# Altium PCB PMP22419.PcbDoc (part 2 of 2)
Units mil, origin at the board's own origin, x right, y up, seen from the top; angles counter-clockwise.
Board outline 4300 x 2100 mil, 4 copper layers (Top Layer, Signal Layer 1, Signal Layer 2, Bottom Layer), stack 66.4 mil thick; 128 components, 54 nets, 301 pads, 317 vias.
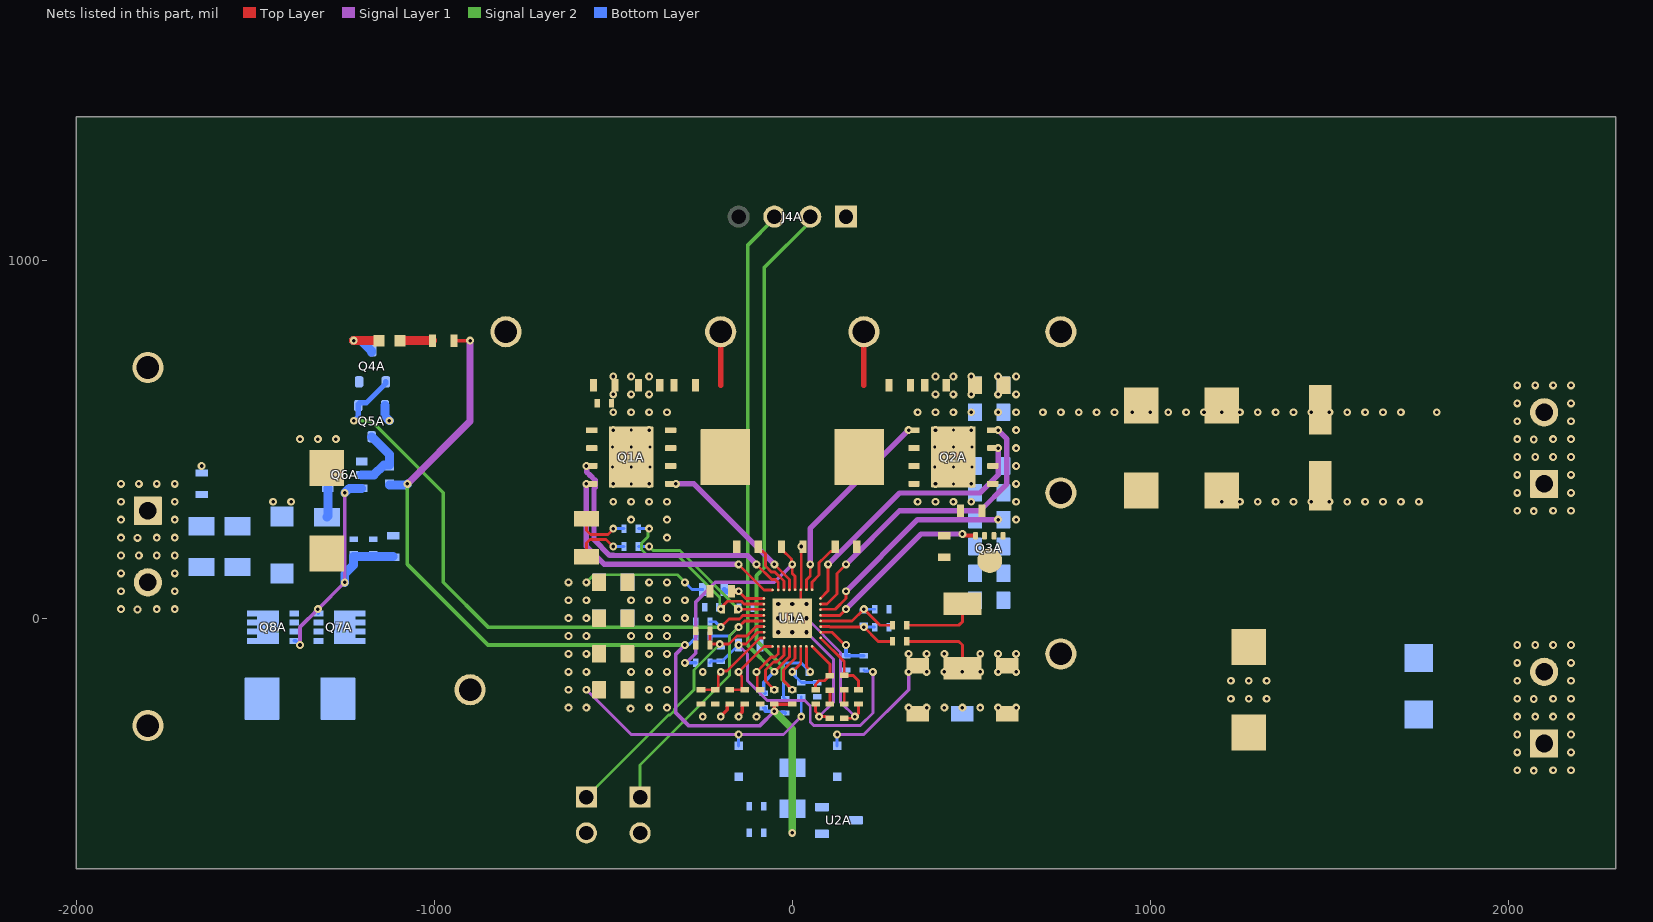
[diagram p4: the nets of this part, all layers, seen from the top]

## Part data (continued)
R31A: library part CMP-0026893-2, "RES, 2.0 M, 5%, 0.063 W, AEC-Q200 Grade 0, 0402", Manufacturer=Vishay-Dale, Power_W=63mW, Supplier Part Number 1=541-2.0MJCT-ND, TempCo="200 ppm/C", Tolerance_%=5%, Value2=0.063W, Value_Code=2M00, ValueDisplayed=2.0M
SH-JP1A: library part CMP-0003623-3, "Shunt, 100mil, Gold plated, Black", Alternate Manufacturer=3M, Alternate PartNumber=969102-0000-DA, Manufacturer=Samtec, Supplier Part Number 1=SAM8858-ND
TP1A TP2A: library part CMP-0055149-1, "Test Point, Multipurpose, White, TH", Color=White, Manufacturer=Keystone, Supplier Part Number 1=36-5012-ND
TP3A TP4A TP8A: library part CMP-0055148-1, "Test Point, Multipurpose, Black, TH", Color=Black, Manufacturer=Keystone, Supplier Part Number 1=36-5011-ND
TP5A TP6A TP7A TP9A: library part CMP-0055147-1, "Test Point, Multipurpose, Red, TH", Color=Red, Manufacturer=Keystone, Supplier Part Number 1=36-5010-ND
U1A: library part CMP-0089011-2, "No description", Manufacturer="Texas Instruments", Operating Temperature Range=to
U2A: library part CMP-0071020-1, "100 mA, Quasi Low-Dropout Linear Voltage Regulator, 3-pin SOT-23, Pb-Free", Manufacturer="Texas Instruments", PackageTopMarking=L0A*XTT, PartNumber=LM3480IM3-3.3/NOPB, PowerWise=N, Supplier Part Number 1=LM3480IM3-3.3TR-ND
Z1A: library part CMP-0085013-1, "Diode, TVS, Bi, 26 V, 42.1 Vc, 400 W, 9.5 A, SMA (non-polarized)", Manufacturer=Littelfuse, Value1=42.1V
ZZ1: library part CMP-0003616-3
ZZ2: library part CMP-0077236-1, Alternate Manufacturer=-
ZZ3: library part CMP-0077237-1, Alternate Manufacturer=-
ZZ4: library part CMP-0077238-1, Alternate Manufacturer=-

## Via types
v1: diameter 22, hole 10, Top Layer to Bottom Layer, tented both sides, 291 vias
v2: diameter 19.68, hole 7.87, Top Layer to Bottom Layer, 16 vias
v3: diameter 23.62, hole 11.81, Top Layer to Bottom Layer, 9 vias
v4: diameter 22, hole 10, Top Layer to Bottom Layer, tented top, 1 vias

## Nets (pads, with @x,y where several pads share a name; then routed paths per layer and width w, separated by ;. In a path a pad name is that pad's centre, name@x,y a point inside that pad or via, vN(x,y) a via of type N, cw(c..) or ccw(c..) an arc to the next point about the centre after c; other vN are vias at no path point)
3V3_1: C51A.2 R1A.2 R16A.1 R17A.2 R18A.2 R25A.2 R26A.1 R34A.2 R35A.1 U2A.1 | length 2752.5
  Top Layer w10: R1A.2@-945,775 v1(-900,775) ; v1(-50,-260) R16A.1@-50,-240 R17A.2@0,-240
  Signal Layer 1 w10: v1(-300,-75) -325,-100 -325,-265 -290,-300 -90,-300 v1(-50,-260)
  Signal Layer 1 w20: v1(-1075,375) -900,550 v1(-900,775)
  Signal Layer 2 w10: v1(-1075,375) -1075,150 -850,-75 v1(-300,-75)
  Signal Layer 2 w20: v1(-50,-260) 0,-310 v1(0,-600)
  Bottom Layer w10: v1(-300,-75) -297.7,-72.7 -288.2,-72.7 -270,-54.5 R26A.1@-270,-50 R25A.2@-270,-10 ; R34A.2@-80,-250 -77.5,-250 -75,-252.5 -75,-260 v1(-50,-260) -46.75,-260 -44.25,-262.5 -22.5,-262.5 R35A.1@-20,-265
  Bottom Layer w25: -1125,372.44 -1077.56,372.44 v1(-1075,375)
BAT_1: C20A.1 C22A.1 C23A.1 C24A.1 D2A.1 D3A.2 J3A.2 R6A.2 R9A.2 TP6A.1 | length 558.7
  Top Layer w8: R9A.2@319.5,-65 465,-65 475,-75 R6A.2@475,-140.55
  Signal Layer 1 w9: v1(125,-325) 200,-325 325,-200 v1(325,-150)
  Bottom Layer w9: D3A.2@125,-356.69 v1(125,-325)
  other v1: 2071.08,-225.95 2025,-225 2125,-225 2175,-225 1225,-175 1275,-175 1325,-175 2025,-175 2175,-175 375,-150 425,-150 475,-150 525,-150 575,-150 625,-150 2025,-125 2175,-125 325,-100 375,-100 425,-100 525,-100 575,-100 625,-100 2025,-75 2075,-75 2125,-75 2175,-75
CHG_OK_1: Q4A.1 Q5A.1 R25A.1 U1A.4 | length 1745.1
  Top Layer w8: v1(-200,-25) -177.01,-2.01 -147.31,-2.01 -137.43,7.87 U1A.4@-79.15,7.87
  Signal Layer 2 w10: v1(-1224.51,551.29) -1176.29,551.29 -975,350 -975,100 -850,-25 v1(-200,-25)
  Bottom Layer w8: R25A.1@-230,-10 -215,-10 v1(-200,-25) -197.32,-22.32 v1@-192.82,-22.32
  Bottom Layer w15: v1(-1224.51,551.29) -1212.4,563.4 Q5A.1@-1212.4,593.31 -1212.4,597.24 -1208.09,601.56 -1189.7,601.56 -1135.2,656.06 Q4A.1@-1135.2,660
GND: C3A.2 C4A.2 C5A.2 C6A.2 C7A.2 C8A.2 C9A.2 C10A.2 C12A.2 C14A.2 C15A.2 C16A.2 C17A.2 C19A.2 C20A.2 C21A.2 C22A.2 C23A.2 C24A.2 C25A.2 C26A.2 C27A.1 C28A.2 C29A.1 C30A.2 C31A.2 C32A.2 C33A.2 C34A.2 C35A.2 C36A.2 C37A.2 C38A.2 C39A.2 C41A.2 C42A.2 C43A.2 C44A.2 C45A.2 C46A.2 C48A.2 C49A.2 C50A.1 C51A.1 D2A.2 J1A.2 J2A.1 J3A.1 J4A.1 JP1A.2 JP2A.2 Q1A.9 Q2A.9 Q4A.2 Q5A.2 Q6A.6 R2A.1 R3A.1 R10A.2 R13A.1 R14A.1 R15A.2 R22A.1 R29A.1 R32A.1 TP3A.1 TP4A.1 TP8A.1 U1A.27 U1A.33 U2A.3 Z1A.2 | length 1111.5
  Top Layer w8: v3(0,0) 23.62,23.62 U1A.27@23.62,79.15 25,80.53 25,195 C12A.2@27.5,197.5 ; v1(25,200) C12A.2@30,200 ; C27A.1@65,-240 65,-261.21 75,-271.21 v1(75,-275) 92.31,-275 93.81,-276.5 101.5,-276.5 C29A.1@105,-280 ; C30A.2@145,-279.69 171.51,-279.69 185,-266.19 C28A.2@185,-240 C28A.2@185,-239.69
  Top Layer w10: v1(-200,-275) -200,-274.23 -182,-256.23 -182,-242.5 -179.5,-240 R14A.1@-175,-240 ; v1(-150,-275) -150,-271.75 -140.19,-261.95 -140.19,-242.5 -137.69,-240 C26A.2@-133.19,-240
  Signal Layer 1 w8: v3(39.37,-39.37) 115,-115 115,-235 v1(75,-275) ; v3(39.37,0) 135,-95.63 135,-235 v1(175,-275)
  Bottom Layer w25: Q5A.2@-1137.6,593.31 -1137.6,563.4 v1(-1125.49,551.29)
  other v1: 2071.08,-425.95 2025,-425 2125,-425 2175,-425 2025,-375 2175,-375 2025,-325 2175,-325 -250,-275 -100,-275 2025,-275 2075,-275 2125,-275 2175,-275 -451.54,-252.73 -400,-250 -350,-250 325,-250 375,-250 425,-250 475,-250 525,-250 575,-250 625,-250 1225,-225 1275,-225 1325,-225 -400,-200 -350,-200 -450,-150 -400,-150 -350,-150 -250,-150 -400,-100 -350,-100 -450,-50 -400,-50 -350,-50 -400,0 -350,0 -300,0 -450,50 -400,50 -350,50 -300,50 -400,100 -350,100 -1828.92,224.05 -1875,225 -1775,225 -1725,225 -350,225 -1875,275 -1725,275 -450,275 -350,275 -1875,325 -1725,325 -1450,325 -1400,325 -500,325 -450,325 -400,325 -350,325 350,325 400,325 450,325 500,325 -1875,375 -1825,375 -1775,375 -1725,375 -500,375 -400,375 400,375 500,375 -1650,425 2071.08,499.05 -1375,500 -1325,500 -1275,500 2025,500 2125,500 2175,500 -500,525 -400,525 400,525 500,525 2025,550 2175,550 -500,575 -450,575 -400,575 -350,575 350,575 400,575 450,575 500,575 700,575 750,575 800,575 850,575 900,575 950,575 1000,575 1050,575 1100,575 1150,575 1200,575 1250,575 1300,575 1350,575 1400,575 1450,575 1500,575 1550,575 1600,575 1650,575 1700,575 1800,575 2025,600 2175,600 -500,625 -450,625 -400,625 400,625 450,625 500,625 2025,650 2075,650 2125,650 2175,650 -500,675 -450,675 -400,675 400,675 450,675 500,675
  other v2: -450,374.8 450,374.8 -502.28,422.24 -450,422.24 -397.72,422.24 397.72,422.24 450,422.24 502.28,422.24 -502.28,477.76 -450,477.76 -397.72,477.76 397.72,477.76 450,477.76 502.28,477.76 -450,525.2 450,525.2
  other v3: -39.37,-39.37 0,-39.37 -39.37,0 -39.37,39.37 0,39.37 39.37,39.37
ILIM_HIZ_1: C21A.1 JP1A.1 R10A.1 R27A.1 U1A.6 | length 807.1
  Top Layer w8: R10A.1@-230,-35 C21A.1@-230,-75 -227.5,-72.5 v1(-202.5,-72.5) -177.2,-72.5 -154.7,-50 -127.25,-50 -100.87,-23.62 U1A.6@-78.74,-23.62
  Signal Layer 2 w8: JP1A.1@-575,-500 -346,-271 -341.3,-271 -329,-258.7 -329,-254 -275,-200 -275,-145 -205,-75 v1@-200,-75
  Bottom Layer w10: v1(-202.5,-72.5) -202.5,-77.5 R27A.1@-200,-80
INPUT_1: J2A.2 J5A.1 Q8A.5 Q8A.6 Q8A.7 Q8A.8 Q8A.9 R20A.2 R21A.2 TP7A.1
  other v1: -1828.92,24.05 -1875,25 -1775,25 -1725,25 -1875,75 -1725,75 -1875,125 -1725,125 -1875,175 -1825,175 -1775,175 -1725,175
NetC1A_1: C1A.1 C11A.2 L1A.1 Q1A.6 Q1A.7 Q1A.8 TP1A.1 | length 157.5
  Top Layer w8: C11A.2@-155,192.5 C11A.2@-155,200
  Top Layer w15: -200,650 TP1A.1@-200,800
NetC1A_2: C1A.2 R2A.2
NetC2A_1: C2A.1 C13A.2 L1A.2 Q2A.6 Q2A.7 Q2A.8 TP2A.1 | length 150
  Top Layer w15: 200,650 TP2A.1@200,800
NetC2A_2: C2A.2 R3A.2
NetC8A_1: C8A.1 C10A.1 Q1A.1 Q1A.2 R4A.2 R5A.2 | length 150.2
  Top Layer w8: R4A.2@-575,278.15 -575,245 -564,234 -514.59,234 -500,248.59 v1(-500,250)
  Bottom Layer w8: v1(-500,250) R5A.2@-470,250
NetC11A_1: C11A.1 U1A.30 | length 160.9
  Top Layer w8: C11A.1@-95,200 -95,192.5 -89,186.5 -81.5,186.5 -75,180 -75,145.3 -58.7,129 -49,129 -23.62,103.62 U1A.30@-23.62,78.74
NetC13A_1: C13A.1 U1A.25 | length 151.9
  Top Layer w8: U1A.25@55.12,79.15 55.12,100.31 75,120.2 75,154.7 91.3,171 106.8,186.5 114,186.5 120,192.5 C13A.1@120,200
NetC15A_1: C15A.1 R24A.2 U1A.1 | length 143.2
  Top Layer w8: v1(-150,75) -130.12,55.12 U1A.1@-79.15,55.12
  Top Layer w15: C15A.1@-170,75 v1(-150,75)
  Top Layer w20: v1@-150.38,75.38 v1(-150,75)
  Bottom Layer w15: R24A.2@-190,80 -190,77.5 -187.5,75 v1(-150,75)
NetC16A_1: C16A.1 Q3A.5-6-7-8 R6A.1 R8A.2 | length 209.7
  Top Layer w8: R8A.2@320,-20 465,-20 475,-10 R6A.1@475,40.55
NetC18A_1: C18A.1 C44A.1 R7A.1 U1A.3 | length 427.8
  Top Layer w8: C18A.1@-155,30 C18A.1@-152.5,27.5 ; v1(-150,25) -80.53,25 U1A.3@-79.15,23.62
  Signal Layer 2 w8: v1(-400,200) -399.31,200 -388.31,189 -314,189 v1(-150,25)
  Bottom Layer w8: R7A.1@-430,200 v1(-400,200) ; C44A.1@-150.24,25.24 v1(-150,25)
NetC18A_2: C18A.2 C43A.1 R5A.1 U1A.2 | length 539.8
  Top Layer w8: v1(-200,25) -200,27.84 -180.84,47 -142.3,47 -134.67,39.37 U1A.2@-79.15,39.37
  Signal Layer 2 w8: v1(-400,250) -402.68,247.32 -402.68,227.53 -419.78,210.43 -419.78,209.92 -421,208.7 -421,191.3 -404.7,175 -319.8,175 -202.68,57.88 -202.68,27.68 v1(-200,25)
  Bottom Layer w8: R5A.1@-430,250 v1(-400,250)
NetC25A_1: C25A.1 R13A.2 U1A.8 | length 259.4
  Top Layer w8: R13A.2@-255,-200 -210.5,-200 -207,-196.5 -207,-160.79 -200,-153.79 v1(-200,-150) -197.32,-147.32 -182.32,-147.32 -90.12,-55.12 U1A.8@-78.74,-55.12
NetC26A_1: C26A.1 R14A.2 U1A.9 | length 225.6
  Top Layer w8: R14A.2@-175,-200 C26A.1@-133.19,-200 -137.69,-200 -141.19,-196.5 -141.19,-162.59 -150,-153.79 v1(-150,-150) -79.15,-79.15 U1A.9@-55.12,-79.15
NetC27A_2: C27A.2 R12A.2 U1A.16 | length 168.2
  Top Layer w8: U1A.16@55.12,-78.74 105,-128.62 R12A.2@105,-161.1 104.22,-161.1 90.31,-175 75,-175 65,-185 C27A.2@65,-200.31
NetC28A_1: C28A.1 R11A.1 U1A.17 | length 203.6
  Top Layer w8: U1A.17@79.15,-55.12 145,-120.97 R11A.1@145,-160 ; R11A.1@145,-160.31 170.32,-160.31 185,-175 C28A.1@185,-200 C28A.1@185,-200.31
NetC29A_2: C29A.2 R12A.1 | length 40.6
  Top Layer w8: C29A.2@105,-240.31 R12A.1@105,-199.69
NetC30A_1: C30A.1 R11A.2 | length 40.6
  Top Layer w8: C30A.1@145,-240.31 R11A.2@145,-199.69
NetC34A_1: C34A.1 R20A.1 R21A.1
NetC40A_1: C40A.1 Q6A.4 Q7A.4 Q8A.4 R22A.2 R23A.1 | length 754.9
  Signal Layer 1 w10: v1(-1375,-75) -1375,-25 v1(-1325,25) v1(-1250,100) v1(-1250,350)
  Bottom Layer w10: Q8A.4@-1390.94,-63.39 -1386.61,-63.39 v1(-1375,-75) ; v1(-1325,25) -1323.82,23.82 Q7A.4@-1323.82,13.39
  Bottom Layer w25: v1(-1250,100) -1250,123.6 -1225,148.6 -1225,172.44 R22A.2@-1115,172.44 ; v1(-1250,350) -1237.4,362.6 Q6A.4@-1202.76,362.6
NetC40A_2: C40A.2 Q7A.1 Q7A.2 Q7A.3 Q8A.1 Q8A.2 Q8A.3 R19A.2 R23A.2 Z1A.1
NetC45A_1: C45A.1 C47A.2 R8A.1 U1A.20 | length 267.2
  Top Layer w8: U1A.20@79.15,-7.87 167.13,-7.87 v1(200,25) 203.73,21.27 245,-20 R8A.1@280.27,-20
  Bottom Layer w8: C47A.2@202.68,22.32 v1(200,25) C45A.1@230,25
NetC47A_1: C47A.1 C48A.1 R9A.1 U1A.19 | length 246.8
  Top Layer w8: U1A.19@79.15,-23.62 103.62,-23.62 105,-25 v1(200,-25) 240,-65 R9A.1@278.83,-65
  Bottom Layer w8: v1(200,-25) C48A.1@230,-25
NetC50A_2: C50A.2 R36A.1 U2A.2
NetD1A_1: D1A.1 R1A.1 | length 90.5
  Top Layer w25: D1A.1@-1095.47,775 R1A.1@-1005,775
NetD1A_2: D1A.2 Q4A.3 | length 135.1
  Top Layer w25: v1(-1225,775) D1A.2@-1154.53,775
  Bottom Layer w25: v1(-1225,775) -1204.13,775 -1175,745.87 Q4A.3@-1175,743.31
NetD3A_1: D3A.1 D4A.1 R36A.2
NetQ1A_3: Q1A.3 U1A.31 | length 802.7
  Top Layer w8: v1(-100,150) -57.6,107.6 -47.4,107.6 -39.37,99.57 U1A.31@-39.37,78.74
  Signal Layer 1 w15: v1(-575,425) -574.34,424.34 -574.34,408.29 -565.55,399.5 -564.85,399.5 -550.5,385.15 -550.5,364.85 -554,361.35 -554,219.35 -510.15,175.5 -500.5,175.5 -500,175 -125,175 v1(-100,150)
NetQ1A_4: Q1A.4 U1A.32 | length 745.1
  Top Layer w8: v1(-150,150) -78.74,78.74 U1A.32@-55.12,78.74
  Signal Layer 1 w15: v1(-575,375) -575,300 -575,283.29 -575,200 -525,150 -350,150 v1(-150,150)
NetQ1A_5: Q1A.5 U1A.29 | length 456.9
  Top Layer w8: v1(-50,150) -7.87,107.87 U1A.29@-7.87,78.74
  Signal Layer 1 w15: v1(-325,375) -275,375 v1(-50,150)
NetQ2A_3: Q2A.3 U1A.24 | length 757.2
  Top Layer w8: U1A.24@78.74,55.12 100,76.38 v1(100,150)
  Signal Layer 1 w15: v1(100,150) 299.5,349.5 524.5,349.5 575,400 v1(575,475)
NetQ2A_4: Q2A.4 U1A.23 | length 852.9
  Top Layer w8: U1A.23@78.74,39.37 96.82,39.37 125,67.55 125,125 v1(150,150)
  Signal Layer 1 w15: v1(150,150) 300,300 525,300 599.5,374.5 599.5,500.5 v1@575.66,524.34
  other v1: 575,525
NetQ2A_5: Q2A.5 U1A.26 | length 564.2
  Top Layer w8: U1A.26@39.37,79.15 39.37,107.37 50,118 v1(50,150)
  Signal Layer 1 w15: v1(50,150) 50,250 v1(325,525)
NetQ3A_4: Q3A.4 U1A.21 | length 529
  Top Layer w8: U1A.21@78.74,7.87 132.87,7.87 v1(150,25)
  Top Layer w10: v1(475,235) 478.25,235 482.32,230.93 509.72,230.93 510.53,230.12 Q3A.4@511.61,230.12
  Signal Layer 1 w15: v1(150,25) 360,235 v1(475,235)
NetQ5A_3: Q5A.3 Q6A.5 R18A.1 | length 189
  Bottom Layer w25: Q6A.5@-1202.76,400 -1168.49,400 -1140.93,427.56 -1125,427.56 -1125,456.69 Q5A.3@-1175,506.69
NetQ6A_1: Q6A.1 Q6A.2 | length 37.4
  Bottom Layer w25: Q6A.2@-1297.24,400 Q6A.1@-1297.24,437.4
NetQ6A_3: Q6A.3 R19A.1 | length 81.7
  Bottom Layer w25: R19A.1@-1300,282.09 -1297.24,284.84 Q6A.3@-1297.24,362.6
NetR15A_1: R15A.1 U1A.10 | length 158.7
  Top Layer w8: R15A.1@-90,-200 -94.5,-200 -98,-196.5 -98,-152 v1(-100,-150) -58.62,-108.62 -48.62,-108.62 -40,-100 -39.8,-100 -39.37,-99.57 U1A.10@-39.37,-79.15
NetR16A_2: R16A.2 U1A.11 | length 161
  Top Layer w8: v4(-50,-200) -54.5,-200 -58,-196.5 -58,-192 -75,-175 -75,-145 -52.62,-122.62 -42.62,-122.62 -23.62,-103.62 U1A.11@-23.62,-79.15
NetR28A_1: R28A.1 R29A.2 U1A.18 | length 165.6
  Top Layer w8: U1A.18@79.15,-39.37 110.58,-39.37 134.52,-63.31 146.21,-75 v1(150,-75)
  Bottom Layer w10: v1(150,-75) R29A.2@150,-105 R28A.1@200,-105
NetR31A_1: R31A.1 R32A.2 R33A.1 U1A.14 | length 166.1
  Top Layer w8: v1(0,-150) 23.62,-126.38 U1A.14@23.62,-78.74
  Bottom Layer w8: v1(0,-150) 2.68,-152.68 2.68,-157.18 25.5,-180 30,-180 R32A.2@70,-180
NetR31A_2: R31A.2 R35A.2 U1A.15 | length 261.2
  Top Layer w8: U1A.15@39.37,-78.74 39.37,-135.58 50,-146.21 v1(50,-150)
  Bottom Layer w8: R35A.2@-20,-225 -21.5,-225 -25,-221.5 -25,-129.69 -20.31,-125 25,-125 v1(50,-150)
OTG_VAP_1: JP2A.1 R26A.2 U1A.5 | length 761.4
  Top Layer w8: v1(-150,-25) -132.87,-7.87 U1A.5@-78.74,-7.87
  Signal Layer 2 w8: JP2A.1@-425,-500 -425,-410 -175,-160 -175,-50.16 -150,-25.16 v1(-150,-25)
  Bottom Layer w8: R26A.2@-230,-50 -175,-50 v1(-150,-25) v1@-153.79,-25
REGN_1: C12A.1 R30A.1 U1A.28 | length 666.3
  Top Layer w8: C12A.1@-30,200 -30,192.5 -2.68,165.18 -2.68,152.68 v1(0,150) 0,125 7.87,117.13 U1A.28@7.87,79.15
  Signal Layer 1 w10: v1(-300,-125) -296.75,-125 -290.75,-119 -290.63,-119 -270,-98.37 -270,45 -215,100 -50,100 v1(0,150)
  Signal Layer 2 w10: v1@-1.36,151.36 v1(0,150)
  Bottom Layer w10: v1(-300,-125) R30A.1@-270,-125
SCL_1: J4A.2 R17A.1 U1A.13 | length 1570.3
  Top Layer w8: v1(0,-200) -25,-175 -25,-145.3 7.87,-112.43 U1A.13@7.87,-78.74
  Signal Layer 2 w10: v1(0,-200) -28,-172 -28,-133.66 -100,-61.66 -100,118.89 -78,140.89 -78,979.54 50,1107.54 J4A.2@50,1121.56
SDA_1: J4A.3 R34A.1 U1A.12 | length 1501
  Top Layer w8: v1(-50,-149.8) -7.87,-107.67 U1A.12@-7.87,-79.15
  Signal Layer 2 w10: v1(-50,-149.8) -125,-74.8 -125,1041 -50,1116 J4A.3@-50,1121.56
  Bottom Layer w10: R34A.1@-75,-210 -77.5,-210 -80,-207.5 -80,-179.8 v1(-50,-149.8) v1@-47.7,-152.09
VDDA_1: C49A.1 R27A.2 R28A.2 R30A.2 U1A.7 | length 882.7
  Top Layer w8: v1(-150,-75) -147.32,-72.32 -129.77,-72.32 -96.82,-39.37 U1A.7@-78.74,-39.37
  Signal Layer 1 w8: v1(-150,-75) -125,-100 -125,-175 -70,-230 35,-230 50,-245 50,-290 60,-300 190,-300 225,-265 v1(225,-150)
  Bottom Layer w8: R30A.2@-230,-125 -230,-123.5 -226.5,-120 R27A.2@-200,-120 -195.5,-120 -150.5,-75 v1(-150,-75) ; R28A.2@200,-145 202.5,-147.5 222.5,-147.5 v1(225,-150)
VIN_1: C7A.1 C14A.1 C17A.1 C19A.1 C41A.1 C42A.1 C46A.1 D4A.2 J5A.2 Q7A.5 Q7A.6 Q7A.7 Q7A.8 Q7A.9 R4A.1 R7A.2 R24A.1 R33A.2 TP9A.1 | length 1265.4
  Top Layer w8: R4A.1@-575,171.85 -575,210 -565,220 -520,220 v1(-500,200)
  Signal Layer 1 w8: v1(-575,-200) -450,-325 v1(-150,-325) -25,-325 v1(25,-275)
  Signal Layer 2 w8: v1(-575,100) -554,121 -321,121 v1(-300,100)
  Bottom Layer w8: v1(-500,200) R7A.2@-470,200 ; v1(-300,100) -280,80 R24A.1@-250,80 ; D4A.2@-150,-356.69 v1(-150,-325) ; v1(25,-275) R33A.2@25,-220
  other v1: -625,-250 -575,-250 -625,-200 -625,-150 -575,-150 -625,-100 -575,-100 -625,-50 -575,-50 -625,0 -575,0 -625,50 -575,50 -625,100
VSYS_1: C3A.1 C4A.1 C5A.1 C6A.1 C9A.1 C31A.1 C32A.1 C33A.1 C35A.1 C36A.1 C37A.1 C38A.1 C39A.1 J1A.1 Q2A.1 Q2A.2 Q3A.1 Q3A.2 Q3A.3 TP5A.1 U1A.22 | length 612.1
  Top Layer w8: U1A.22@78.74,23.62 80.12,25 120,25 150,55 v1(150,75)
  Signal Layer 1 w15: v1(150,75) 350,275 v1(575,275)
  other v1: 625,275 2071.08,299.05 2025,300 2125,300 2175,300 625,325 1200,325 1250,325 1300,325 1350,325 1400,325 1450,325 1500,325 1550,325 1600,325 1650,325 1700,325 1750,325 2025,350 2175,350 625,375 2025,400 2175,400 625,425 2025,450 2075,450 2125,450 2175,450 625,475 625,525 575,575 625,575 575,625 625,625 575,675 625,675
pads on no net: J4A.4 SH-JP1A.0

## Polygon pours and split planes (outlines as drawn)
NetC8A_1 on Top Layer "Top Layer-VIN" (solid, pour order 213): -650,275 -525,275 -525,700 -650,700 -650,600
NetC2A_2 on Top Layer "NETC2A_2_L01_P223" (solid, pour order 223): 320,675 320,625 380,625 380,675
NetC1A_2 on Top Layer "NETC1A_2_L01_P224" (solid, pour order 224): -380,675 -380,625 -320,625 -320,675
VSYS_1 on Top Layer "Top Layer-VSYS_1" (solid, pour order 225): 525,225 2175,225 2175,450 650,450 650,700 525,700 525,450
NetC2A_1 on Top Layer "Top Layer-NetC24_2" (solid, pour order 226): 300,350 375,350 375,550 300,550 300,700 10,700 10,275 100,275 100,175 250,175 300,225
VIN_1 on Top Layer "Top Layer-VIN 1" (solid, remove dead copper, pour order 260): -1450,-300 -500,-300 -500,175 -650,175 -1175,175 -1175,200 -1450,200
INPUT_1 on Top Layer "INPUT_1_L01_P261" (solid, pour order 261): -1950,200 -1475,200 -1475,-300 -1950,-300
NetC1A_1 on Top Layer "Top Layer-NetC25_2" (solid, pour order 273): -300,550 -375,550 -375,350 -300,350 -300,225 -250,175 -100,175 -100,275 -10,275 -10,700 -300,700
BAT_1 on Top Layer "BAT_1_L01_P281" (solid, pour order 281): 2000,-195 2000,-250 2175,-250 2175,25 650,25 650,-85 275,-85 275,-195
NetC16A_1 on Top Layer "NETC16A_1_L01_P285" (solid, pour order 285): 650,100 650,10 200,10 200,200 650,200
GND on Top Layer "Top Layer-GND" (solid, remove dead copper, pour order 287): -2001.47,-700 2298.53,-700 2298.53,1396.18 -2001.47,1396.18
BAT_1 on Bottom Layer "BAT_1_L04_P214" (solid, pour order 214): 650,-25 650,-225 275,-225 275,-25 475,-25
BAT_1 on Bottom Layer "BAT_1_L04_P215" (solid, remove dead copper, pour order 215): 2000,-210 2000,-250 2175,-250 2175,-10 1200,-10 1200,-210
NetC50A_2 on Bottom Layer "NETC50A_2_L04_P216" (solid, pour order 216): -100,-500 -100,-550 100,-550 100,-500
3V3_1 on Bottom Layer "3V3_1_L04_P218" (solid, pour order 218): -100,-575 -100,-625 104.92,-625 104.92,-575
NetD3A_1 on Bottom Layer "NETD3A_1_L04_P230" (solid, pour order 230): -175,-400 -175,-475 150,-475 150,-400
VSYS_1 on Bottom Layer "VSYS_1_L04_P232" (solid, remove dead copper, pour order 232): 650,275 650,0 550,0 550,275 550,450 550,700 650,700 650,450 2175,450 2175,275
VIN_1 on Bottom Layer "Bottom Layer-VIN" (solid, remove dead copper, pour order 233): -500,-300 -500,175 -525,175 -800,175 -800,225 -1000,225 -1000,150 -1275,150 -1275,-100 -1350,-100 -1350,-300
INPUT_1 on Bottom Layer "INPUT_1_L04_P274" (solid, remove dead copper, pour order 274): -1375,-300 -1375,-100 -1450,-100 -1450,175 -1950,175 -1950,-300
NetC34A_1 on Bottom Layer "NETC34A_1_L04_P275" (solid, remove dead copper, pour order 275): -1700,375 -1700,225 -1500,225 -1500,375
NetC40A_2 on Bottom Layer "NETC40A_2_L04_P277" (solid, remove dead copper, pour order 277): -1250,150 -1250,200 -1100,200 -1100,250 -1450,250 -1450,75 -1400,75 -1400,-75 -1300,-75 -1300,150
GND on Bottom Layer "GND_L04_P284" (solid, pour order 284): -650,700 650,700 650,475 650,250 650,-300 250,-300 -650,-300
GND on Bottom Layer "Bottom Layer-GND" (solid, remove dead copper, pour order 286): -2000,-700 2300,-700 2300,1400 -2000,1400
GND on Signal Layer 2 "Signal Layer 2-GND" (solid, remove dead copper, pour order 283): -2000,-700 2300,-700 2300,1400 -2000,1400
GND on Signal Layer 1 "Signal Layer 1-GND" (solid, remove dead copper, pour order 282): -2006.66,-700 2300,-700 2300,1407.59 -2006.66,1407.59

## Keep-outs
Keep-Out Layer:
  lines w10: -1900,-700 -50,-700 ; 50,-700 2200,-700 ; -2000,-700 2300,-700 ; -2000,-700 -2000,1575 2300,1575 2300,-700 ; -2000,-700 2300,-700
  text ".Layer_Name" at -1443,-4058.49 h30

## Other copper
Top Layer:
  pour cut-out: 45,-190 45,-290 200,-290 200,-190
  text ".Layer_Name" at -1443,-4058.49 h30
Signal Layer 1:
  pour cut-out: 25,15 25,-50 75,-100 100,-125 100,-235 75,-260 60,-260 60,-290 190,-290 190,-260 175,-260 150,-235 150,-95 55,0 55,15
  text ".Layer_Name" at -1443,-4058.49 h30
Signal Layer 2:
  rectangle net GND: -55,-55 55,50
  text ".Layer_Name" at -1443,-4058.49 h30
Bottom Layer:
  text ".Layer_Name" at -1443,-4058.49 h30
Multi-Layer:
  pour cut-out: 60,-260 60,-290 90,-290 90,-260
  pour cut-out: 160,-260 160,-290 190,-290 190,-260

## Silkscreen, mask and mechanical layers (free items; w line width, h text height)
Top Overlay:
  lines w10: -335,-610 -235,-610 -235,-540 -140,-540 ; -650,-300 650,-300 650,700 -650,700 -650,-300
  text "2022" at 745,1120 h50
  text "SDA" at -100,1025 h30
  text "SCL" at 0,1025 h30
  text "GND" at 100,1025 h30
  text "PMP22419 REVA" at 1000,800 h100
  text "PGND" at 1675,650 h30
  text "PGND" at -1875,500 h30
  text "VSYS" at 1675,350 h30
  text "16A MAX" at 2000,150 h30
  text "VIN" at -1825,-100 h30
  text "VBAT" at 1675,-150 h30
  text "10A MAX" at -1875,-175 h30
  text "PGND" at 1675,-450 h30
  text "EN" at -705,-505 h30
  text "16A MAX" at 2000,-570 h30
  text "FWD OTG" at -335,-595 h30
  text ".Layer_Name" at -1443,-4058.49 h30
Bottom Overlay:
  text ".Layer_Name" at -1443,-4058.49 h30
Top Paste:
  text ".Layer_Name" at -1443,-4058.49 h30
Bottom Paste:
  text ".Layer_Name" at -1443,-4058.49 h30
Top Solder:
  rectangle: -125,370 -30,530
  rectangle: 30,370 130,530
  text ".Layer_Name" at -1443,-4058.49 h30
  text ".Layer_Name" at -1443,-4058.49 h30
Bottom Solder:
  text ".Layer_Name" at -1443,-4058.49 h30
Drill Guide:
  text ".Layer_Name" at -1443,-4058.49 h30
M1 Board Outline:
  the board outline again, w10
  text ".Layer_Name" at -1443,-4058.49 h30
M2 Board Dimensions:
  rectangle: -2020,-3475 -1895,-3350
  rectangle: -1895,-3600 -1520,-3475
  lines w7: -2020,-3475 -1020,-3475 ; -1895,-3600 -1895,-3350 ; -1770,-3600 -1770,-3350 ; -1520,-3600 -1520,-3350 ; -1270,-3600 -1270,-3350 ; -2020,-3600 -1020,-3600 -1020,-3350 -2020,-3350 -2020,-3600
  text ".Layer_Name" at -1443,-4058.49 h30
M3 3D STEP Top:
  text ".Layer_Name" at -1443,-4058.49 h30
M4 3D STEP Bottom:
  text ".Layer_Name" at -1443,-4058.49 h30
M5 Assembly Top:
  lines w10: -2312,-4130.17 4288,-4130.17 ; -2312,-3926.83 4290,-3926.83 ; -2312,-3723.5 -2312,-4333.5 1693,-4333.5 4290,-4333.5 4290,-3723.5 -2311.5,-3723.5 -2311.5,-4333.5 -736,-4333.5 ; 153,-4333.5 153,-3723.5 ; 1420,-3926.83 1420,-3723.5 ; 2260,-3926.83 2260,-3723.5 ; 2882,-4340 2882,-4137.17
  text "COMPONENTS MARKED 'DNP' SHOULD NOT BE POPULATED." at -866.5,-3518.5 h30
  text "ASSEMBLY VARIANT:" at -867,-3634 h30
  text ".VariantName" at 169,-3634 h30
  text "PCB VIEWED FROM TOP SIDE" at -2248.5,-3855.67 h30
  text "BOARD #:" at 228,-3855.67 h30
  text ".PRJ_Number" at 773.5,-3855.67 h30
  text "REV:" at 1618,-3855.67 h30
  text ".PCB_Rev" at 1909.5,-3855.67 h30
  text "SVN REV:" at 2456,-3855.67 h30
  text ".VersionControl_RevNumber" at 2962,-3855.67 h30
  text "TID #:" at 228,-4059 h30
  text ".TID" at 773.5,-4059 h30
  text "PLOT NAME =" at -2248.5,-4264.34 h30
  text ".plot_File_Name" at -1443,-4264.34 h30
  text "GENERATED    :" at 230,-4264.34 h30
  text ".Print_Date" at 1099.5,-4264.34 h30
  text ".Print_Time" at 1828.5,-4264.34 h30
  text "TEXAS INSTRUMENTS" at 3093,-4264.34 h30
M6 Assembly Bottom:
  lines w10: -2312.5,-3927.33 4289.5,-3927.33 ; -2310.5,-4130.67 4289.5,-4130.67 ; -904.5,-4340.5 -904.5,-4137.67 ; -282.5,-3927.33 -282.5,-3724 ; 557.5,-3927.33 557.5,-3724 ; 1824.5,-4334 1824.5,-3724 ; 2713.5,-4334 4289,-4334 4289,-3724 -2312.5,-3724 -2312.5,-4334 284.5,-4334 4289.5,-4334 4289.5,-3724
  text "COMPONENTS MARKED 'DNP' SHOULD NOT BE POPULATED." at 4082,-3518 h30
  text ".VariantName" at 3038,-3634 h30
  text "ASSEMBLY VARIANT:" at 4077,-3634 h30
  text ".VersionControl_RevNumber" at -984.5,-3856.17 h30
  text "SVN REV:" at -478.5,-3856.17 h30
  text ".PCB_Rev" at 68,-3856.17 h30
  text "REV:" at 359.5,-3856.17 h30
  text ".PRJ_Number" at 1204,-3856.17 h30
  text "BOARD #:" at 1749.5,-3856.17 h30
  text "PCB VIEWED FROM BOTTOM SIDE" at 4226,-3856.17 h30
  text ".TID" at 1204,-4059.5 h30
  text "TID #:" at 1749.5,-4059.5 h30
  text "TEXAS INSTRUMENTS" at -1115.5,-4264.84 h30
  text ".Print_Time" at 149,-4264.84 h30
  text ".Print_Date" at 878,-4264.84 h30
  text "GENERATED    :" at 1747.5,-4264.84 h30
  text ".plot_File_Name" at 3420.5,-4264.84 h30
  text "PLOT NAME =" at 4226,-4264.84 h30
M9 Title Sheet:
  drawing of 58 lines, arcs and shapes, not listed
  text "1" at -1280.16,4836.5 h70
  text "2" at 1215.5,4836.5 h70
  text "3" at 3704.84,4836.5 h70
  text "4" at 6211.51,4836.5 h70
  text "5" at 8710.5,4836.5 h70
  text "6" at 11215.5,4836.5 h70
  text "A" at -2436.5,3693.5 h70
  text "A" at 12363.5,3693.5 h70
  text "B" at -2436.5,1313.5 h70
  text "B" at 12363.5,1313.5 h70
  text "C" at -2436.5,-1061.5 h70
  text "C" at 12363.5,-1061.5 h70
  text "PROJECT TITLE:" at 9323.5,-2922.5 h45
  text ".PRJ_Title" at 9373.5,-3055.83 h70
  text "DESIGNED FOR:" at 9323.5,-3223.5 h45
  text ".PRJ_Customer" at 9373.5,-3363.5 h70
  text "D" at -2436.5,-3431.5 h70
  text "D" at 12363.5,-3431.5 h70
  text "FILE NAME:" at 9323.5,-3523.5 h45
  text ".PCB_File_Name_No_Path" at 9373.5,-3643.5 h70
  text "Texas Instruments (TI) and/or its licensors do not warrant the accuracy or completeness of this specification" at 4354,-3805.34 h45
  text "ENGINEER:" at 9323.5,-3813.5 h45
  text "LAYOUT BY:" at 10828.5,-3813.5 h45
  text "or any information contained therein. TI and/or its licensors do not warrant that this design will meet" at 4309.01,-3918 h45
  text ".PRJ_Engineer" at 9373.5,-3968.49 h70
  text ".PCB_Layout" at 10879,-3968.49 h70
  text "the specifications, will be suitable for your application or fit for any particular purpose, or will operate in" at 4309.01,-4030.67 h45
  text ".Layer_Name" at -1443,-4058.49 h30
  text "ALTIUM DESIGNER VERSION:" at 10828.5,-4123.5 h45
  text "an implementation. TI and/or its licensors do not warrant that the design is production worthy. You should" at 4309.01,-4143.33 h45
  text "completely validate and test your design implementation to confirm the system functionality for your application." at 4354,-4256 h45
  text ".print_Scale" at 9373.5,-4256.83 h70
  text ".Application_BuildNumber" at 10879,-4256.83 h70
  text "1" at -1280.16,-4463.5 h70
  text "2" at 1215.5,-4463.5 h70
  text "3" at 3704.84,-4463.5 h70
  text "4" at 6211.51,-4463.5 h70
  text "5" at 8710.5,-4463.5 h70
  text "6" at 11215.5,-4463.5 h70
M10 Fab Notes:
  drawing of 185 lines, arcs and shapes, not listed
  text "DESIGN INFORMATION" at 10361.02,2710 h30
  text "MIN. TRACK WIDTH:" at 9716.46,2530 h30
  text "8" at 10812.7,2530 h30
  text "MIL" at 10967.46,2530 h30
  text "MIN. CLEARANCE:" at 9716.46,2398 h30
  text "6" at 10752.7,2398 h30
  text "MIL" at 10967.46,2398 h30
  text "MIN. VIA PAD SIZE:" at 9716.46,2266 h30
  text "18" at 10782.71,2266 h30
  text "MIL" at 10967.46,2266 h30
  text "0.05mm (2MIL)" at 10411.46,2124.29 h30
  text "MINIMUM ANNULAR RING" at 9387.23,2120 h30
  text "EXTERNAL" at 11119.46,2120 h30
  text "PER" at 9587.23,2002 h30
  text "IPC-D-275 CLASS 2 LEVEL C" at 9807.23,2002 h30
  text "MIL, HOLES" at 11295.46,1889.71 h30
  text "+/-" at 10903,1889 h30
  text "+/-" at 11757,1889 h30
  text "REGISTRATION TOLERANCES:" at 9387.23,1884 h30
  text "METAL" at 10587,1884 h30
  text "5" at 11163.2,1884 h30
  text "3" at 11996.2,1884 h30
  text "MIL" at 12112.46,1884 h30
  text "MATERIAL:" at 9312.46,1674.54 h30
  text "FR-4 High Tg" at 10298.9,1534.21 h30
  text "FR-408" at 9733.46,1525.64 h30
  text "X" at 10145.46,1525.64 h30
  text "OTHER" at 11221.46,1525.64 h30
  text "67.2 MIL (1.71mm) +/-10%" at 10053.56,1362.92 h30
  text "THICKNESS:" at 9387.23,1358.64 h30
  text "X" at 9925.4,1358.64 h30
  text "OTHER" at 11338.46,1358.64 h30
  text "TOLERANCE:" at 9387.23,1200.64 h30
  text "X" at 10226.53,1200.64 h30
  text "ANSI IPC-6012 TYPE 3 CLASS 2" at 10413.48,1200.64 h30
  text "OTHER +/-" at 10413.46,1044.64 h30
  text "BOW & TWIST:" at 9387.23,887.64 h30
  text "X" at 10226.53,887.64 h30
  text "ANSI IPC-6012 TYPE 3 CLASS 2" at 10413.48,887.64 h30
  text "OTHER +/-" at 10413.46,729.13 h30
  text "DRILLING:" at 9312.46,590.64 h30
  text "REFERENCE:" at 9387.23,473.64 h30
  text "X" at 10035.46,473.64 h30
  text "AS SHOWN" at 10222.46,473.64 h30
  text "X" at 10936.46,473.64 h30
  text "NC_DRILL FILES" at 11073.46,473.64 h30
  text "PTH MIN COPPER THICKNESS:" at 9387.23,315.64 h30
  text "X" at 10737.46,315.64 h30
  text "1MIL" at 10874.46,315.64 h30
  text "OTHER" at 11371.46,315.64 h30
  text "BOARD FINISH:" at 9312.46,156.64 h30
  text "SILKSCREEN:" at 9467.68,38.64 h30
  text "X" at 10416.46,38.64 h30
  text "TOP" at 10542.46,38.64 h30
  text "X" at 10926.46,38.64 h30
  text "BOTTOM" at 11053.46,38.64 h30
  text "SILKSCREEN COLOR:" at 9467.68,-128.36 h30
  text "X" at 10415.42,-128.36 h30
  text "WHITE" at 10542.46,-128.36 h30
  text "OTHER" at 11053.46,-128.36 h30
  text "SOLDER RESIST COLOR:" at 9467.68,-298.36 h30
  text "X" at 10035.42,-457.56 h30
  text "GREEN" at 10162.46,-457.56 h30
  text "BLUE" at 10753.46,-457.56 h30
  text "OTHER" at 11291.46,-457.56 h30
  text "IMMERSION GOLD (ENIG)" at 10373.46,-646.08 h30
  text "ENEPIG" at 11711,-649.36 h30
  text "SURFACE FINISH:" at 9312.46,-650.36 h30
  text "X" at 10186.51,-650.36 h30
  text "IMM. TIN/SILVER OR EQUIV" at 9642,-807.36 h30
  text "OTHER" at 11073.46,-807.36 h30
  text "ARRAY/PANEL:" at 9312.46,-986.36 h30
  text "CUT AND TRIM PER MECH LAYER 1" at 10373.46,-990.65 h30
  text "N.C. ROUTE" at 10373.46,-1142.36 h30
  text "X" at 11052.46,-1142.36 h30
  text "V. SCORE" at 11239.46,-1142.36 h30
  text "CERTIFICATION:" at 9312.46,-1279.36 h30
  text "MATERIALS AND WORKMANSHIP FOR ALL PCBS" at 10037.46,-1279.36 h30
  text "TO MEET OR EXCEED THE REQUIREMENTS OF:" at 10037.46,-1377.36 h30
  text "X" at 9663.96,-1513.87 h30
  text "ANSI IPC-A-600F CLASS ->" at 9802.96,-1513.87 h30
  text "X" at 11442.02,-1513.87 h30
  text "2" at 11560.96,-1513.86 h30
  text "1" at 11245.96,-1515.36 h30
  text "3" at 11914.96,-1515.36 h30
  text "X" at 9666.02,-1673.36 h30
  text "UL 94V-0" at 9802.96,-1673.36 h30
  text "X" at 10478.02,-1673.36 h30
  text "RoHS" at 10614.96,-1673.36 h30
  text "OTHER" at 11259.36,-1673.36 h30
  text "PER ORDER" at 11656.42,-1673.36 h30
  text "ADDITIONAL REQUIREMENTS:" at 9312.46,-1814.36 h30
  text "MICROSECTION:" at 9387.23,-1929.36 h30
  text "YES" at 10292.96,-1929.36 h30
  text "REQUIRED" at 11154.46,-2085.51 h30
  text "BARE BOARD ELEC. TEST:" at 9387.23,-2088.36 h30
  text "NONE" at 10692.96,-2088.36 h30
  text "X" at 11027.46,-2088.36 h30
  text "PER ORDER" at 11746.46,-2088.36 h30
  text "MANUFACTURER'S UL:" at 9387.23,-2245.36 h30
  text "RAIL" at 10552.96,-2249.65 h30
  text "METAL" at 11044.77,-2249.65 h30
  text "X" at 11420,-2250 h30
  text "SILK" at 11556.46,-2249.65 h30
  text ".Layer_Name" at -1443,-4058.49 h30
M11 Gerber Information:
  lines w10: -2312,-4130.17 4288,-4130.17 ; -2312,-3926.83 4290,-3926.83 ; -2312,-3723.5 -2312,-4333.5 1693,-4333.5 4290,-4333.5 4290,-3723.5 -2311.5,-3723.5 -2311.5,-4333.5 -736,-4333.5 ; 153,-4333.5 153,-3723.5 ; 1420,-3926.83 1420,-3723.5 ; 2260,-3926.83 2260,-3723.5 ; 2882,-4340 2882,-4137.17
  text "ALL ARTWORK VIEWED FROM TOP SIDE" at -2248.5,-3855.67 h30
  text "BOARD #:" at 228,-3855.67 h30
  text ".PRJ_Number" at 773.5,-3855.67 h30
  text "REV:" at 1618,-3855.67 h30
  text ".PCB_Rev" at 1909.5,-3855.67 h30
  text "SVN REV:" at 2456,-3855.67 h30
  text ".VersionControl_RevNumber" at 2962,-3855.67 h30
  text "LAYER NAME =" at -2248.5,-4058.49 h30
  text "TID #:" at 228,-4059 h30
  text ".TID" at 773.5,-4059 h30
  text "PLOT NAME =" at -2248.5,-4264.34 h30
  text ".plot_File_Name" at -1443,-4264.34 h30
  text "GENERATED    :" at 230,-4264.34 h30
  text ".Print_Date" at 1099.5,-4264.34 h30
  text ".Print_Time" at 1828.5,-4264.34 h30
  text "TEXAS INSTRUMENTS" at 3093,-4264.34 h30
M12 Stackup:
  drawing of 295 lines, arcs and shapes, not listed
  text "Layer" at 4275.44,1504.84 h30
  text "Name" at 4490.4,1504.84 h30
  text "Material" at 4970.27,1504.84 h30
  text "Thickness" at 5410.15,1504.84 h30
  text "Constant" at 5745.07,1504.84 h30
  text "Board Layer Stack" at 6040,1504.84 h30
  text "Top Overlay" at 4490.4,1444.84 h30
  text "Top Solder" at 4490.4,1384.84 h30
  text "Solder Resist" at 4970.27,1384.84 h30
  text "0.40mil" at 5410.15,1384.84 h30
  text "3.5" at 5745.07,1384.84 h30
  text "1" at 4275.44,1324.84 h30
  text "Top Layer" at 4490.4,1324.84 h30
  text "2.80mil" at 5410.15,1324.84 h30
  text "Dielectric1" at 4490.4,1264.84 h30
  text "FR-4 High TG" at 4970.27,1264.84 h30
  text "12.60mil" at 5410.15,1264.84 h30
  text "4.2" at 5745.07,1264.84 h30
  text "2" at 4275.44,1204.84 h30
  text "Signal Layer 1" at 4490.4,1204.84 h30
  text "2.80mil" at 5410.15,1204.84 h30
  text "Dielectric 2" at 4490.4,1144.84 h30
  text "FR-4 High TG" at 4970.27,1144.84 h30
  text "30.00mil" at 5410.15,1144.84 h30
  text "4.2" at 5745.07,1144.84 h30
  text "3" at 4275.44,1084.84 h30
  text "Signal Layer 2" at 4490.4,1084.84 h30
  text "2.80mil" at 5410.15,1084.84 h30
  text "Dielectric 3" at 4490.4,1024.84 h30
  text "FR-4 High TG" at 4970.27,1024.84 h30
  text "12.60mil" at 5410.15,1024.84 h30
  text "4.2" at 5745.07,1024.84 h30
  text "4" at 4275.44,964.84 h30
  text "Bottom Layer" at 4490.4,964.84 h30
  text "2.80mil" at 5410.15,964.84 h30
  text "Bottom Solder" at 4490.4,904.84 h30
  text "Solder Resist" at 4970.27,904.84 h30
  text "0.40mil" at 5410.15,904.84 h30
  text "3.5" at 5745.07,904.84 h30
  text "Bottom Overlay" at 4490.4,844.84 h30
  text ".Layer_Name" at -1443,-4058.49 h30
M13 Component Bodies Top:
  text ".Layer_Name" at -1443,-4058.49 h30
M14 Component Bodies Bottom:
  text ".Layer_Name" at -1443,-4058.49 h30
M15 Courtyards Top:
  text ".Layer_Name" at -1443,-4058.49 h30
M16 Courtyards Bottom:
  text ".Layer_Name" at -1443,-4058.49 h30
Drill Drawing:
  circle w10: c4324.36,226.67 r16.67
  lines w10: 4307.69,-6.66 4316.03,-6.66 4324.36,-15 4332.69,-6.66 4341.03,-6.66 4332.69,1.67 4341.03,10 4332.69,10 4324.36,18.34 4316.03,10 4307.69,10 4316.03,1.67 4307.69,-6.66 ; 4307.69,93.34 4341.03,93.34 4324.36,60 4307.69,93.34 ; 4307.69,135 4341.03,135 4341.03,168.34 4307.69,168.34 4307.69,135 ; 4307.69,285 4307.69,293.34 4316.03,301.67 4307.69,310 4307.69,318.34 4316.03,318.34 4324.36,310 4332.69,318.34 4341.03,318.34 4341.03,310 4332.69,301.67 4341.03,293.34 4341.03,285 4332.69,285 4324.36,293.34 4316.03,285 4307.69,285 ; 4307.69,360 4324.36,368.34 4341.03,360 4332.69,376.67 4341.03,393.34 4324.36,385 4307.69,393.34 4316.03,376.67 4307.69,360 ; 4314.36,-3.33 4319.36,-3.33 4324.36,-8.33 4329.36,-3.33 4334.36,-3.33 4329.36,1.67 4334.36,6.67 4329.36,6.67 4324.36,11.67 4319.36,6.67 4314.36,6.67 4319.36,1.67 4314.36,-3.33
  lines w15: 4276.23,-37.5 6295.72,-37.5 ; 4276.23,412.5 6295.72,412.5 ; 4567.67,-112.5 4567.67,487.5 ; 4932.58,-112.5 4932.58,487.5 ; 5621.38,-112.5 5621.38,487.5 ; 5890.32,-112.5 5890.32,487.5 ; 4276.23,-112.5 6295.72,-112.5 6295.72,487.5 4276.23,487.5 4276.23,-112.5
  text "Symbol" at 4321.23,435 h36
  text "Hit Count" at 4590.17,435 h36
  text "Finished Hole Size" at 4955.08,435 h36
  text "Plated" at 5643.88,435 h36
  text "Hole Type" at 5912.82,435 h36
  text "6" at 4590.17,360 h30
  text "49.21mil (1.250mm)" at 4955.08,360 h30
  text "PTH" at 5643.88,360 h30
  text "Round" at 5912.82,360 h30
  text "8" at 4590.17,285 h30
  text "40.16mil (1.020mm)" at 4955.08,285 h30
  text "PTH" at 5643.88,285 h30
  text "Round" at 5912.82,285 h30
  text "9" at 4590.17,210 h30
  text "11.81mil (0.300mm)" at 4955.08,210 h30
  text "PTH" at 5643.88,210 h30
  text "Round" at 5912.82,210 h30
  text "9" at 4590.17,135 h30
  text "63.00mil (1.600mm)" at 4955.08,135 h30
  text "PTH" at 5643.88,135 h30
  text "Round" at 5912.82,135 h30
  text "16" at 4590.17,60 h30
  text "7.87mil (0.200mm)" at 4955.08,60 h30
  text "PTH" at 5643.88,60 h30
  text "Round" at 5912.82,60 h30
  text "292" at 4590.17,-15 h30
  text "10.00mil (0.254mm)" at 4955.08,-15 h30
  text "PTH" at 5643.88,-15 h30
  text "Round" at 5912.82,-15 h30
  text "340 Total" at 4590.17,-90 h30
  text ".Layer_Name" at -1443,-4058.49 h30

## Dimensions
-2000,1575 to -2000,-700 on M2 Board Dimensions
-2000,-700 to 2300,-700 on M2 Board Dimensions
-650,700 to 650,700 on M2 Board Dimensions
-650,700 to -650,-300 on M2 Board Dimensions
-2020,-3600 to -1020,-3600 on M2 Board Dimensions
